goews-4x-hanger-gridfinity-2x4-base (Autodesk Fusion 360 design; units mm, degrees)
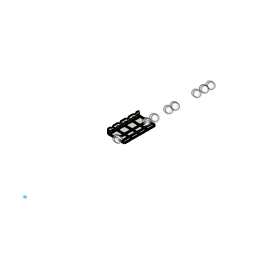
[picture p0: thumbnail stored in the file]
base_feature "Base Feature2"
base_feature "Base Feature1" bodies "Quad Plate Blank"
delete_face "DeleteFace1"
split "Split1" bodies "Quad Plate Blank (1)"
combine "Combine1"
extrude "Extrude1" add sketch "Reconstructed-Sketch1" blind -7
combine "Combine2" bodies "Quad Plate Blank"
chamfer "Chamfer1" distance 4
extrude "Extrude2" cut sketch "Reconstructed-Sketch2" blind -1060
combine "Combine3"
remove_body "RemoveBody1"
remove_body "RemoveBody3"
component_from_bodies "Body->Comp"
remove_body "RemoveBody1"
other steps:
base_feature "Base Feature1"
remove_body "RemoveBody2"
remove_body "RemoveBody4"
create_component "CreateComponent1"
remove_body "RemoveBody5"
named bodies: "Quad Plate Blank", "Quad Plate Blank (1)"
